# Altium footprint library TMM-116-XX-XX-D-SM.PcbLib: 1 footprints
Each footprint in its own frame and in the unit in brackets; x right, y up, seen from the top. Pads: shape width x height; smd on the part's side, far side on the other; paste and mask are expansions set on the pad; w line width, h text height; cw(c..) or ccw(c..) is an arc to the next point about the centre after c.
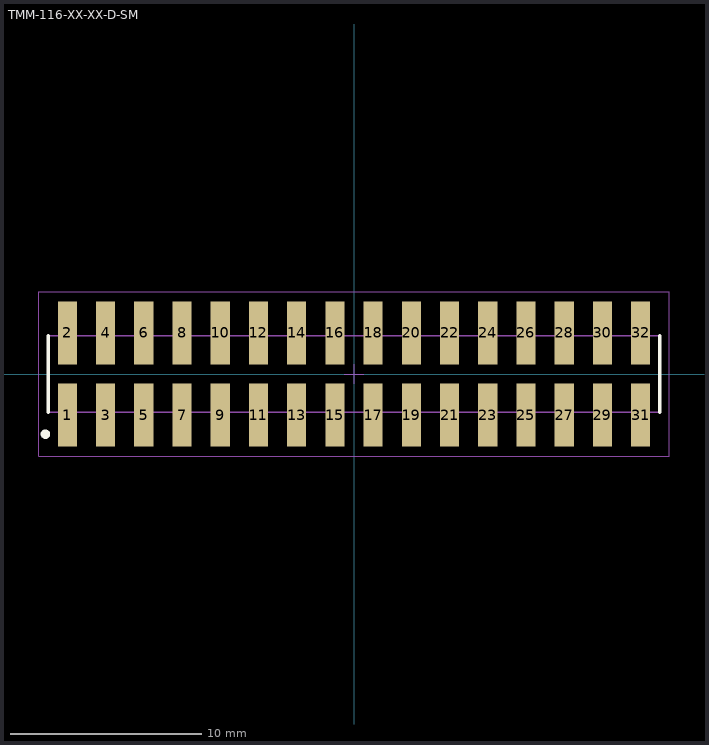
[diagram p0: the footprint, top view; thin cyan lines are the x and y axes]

## TMM-116-XX-XX-D-SM [mm] "2.00mm pitch, 32 pin, terminal strip; double row, SMT"
height 2.77
pads (32):
  rect 1x3.3 smd mask+0: 1(-15,-2.15) 2(-15,2.15) 3(-13,-2.15) 4(-13,2.15) 5(-11,-2.15) 6(-11,2.15) 7(-9,-2.15) 8(-9,2.15) 9(-7,-2.15) 10(-7,2.15) 11(-5,-2.15) 12(-5,2.15) 13(-3,-2.15) 14(-3,2.15) 15(-1,-2.15) 16(-1,2.15) 17(1,-2.15) 18(1,2.15) 19(3,-2.15) 20(3,2.15) 21(5,-2.15) 22(5,2.15) 23(7,-2.15) 24(7,2.15) 25(9,-2.15) 26(9,2.15) 27(11,-2.15) 28(11,2.15) 29(13,-2.15) 30(13,2.15) 31(15,-2.15) 32(15,2.15)
Top Overlay:
  circle w0.25: c-16.15,-3.15 r0.125
  lines w0.2: -16,-2 -16,2 ; 16,-2 16,2
Mechanical 12:
  lines w0.001: -16,-2 16,-2 16,2 -16,2 -16,-2
Mechanical 13:
  lines w0.1: -16,-2 16,-2 16,2 -16,2 -16,-2
  text ".Designator" at 0,-0.127 h1.52
Mechanical 15:
  lines w0.05: -0.5,0 0.5,0 ; 0,-0.5 0,0.5 ; -16.5,-4.3 16.5,-4.3 16.5,4.3 -16.5,4.3 -16.5,-4.3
